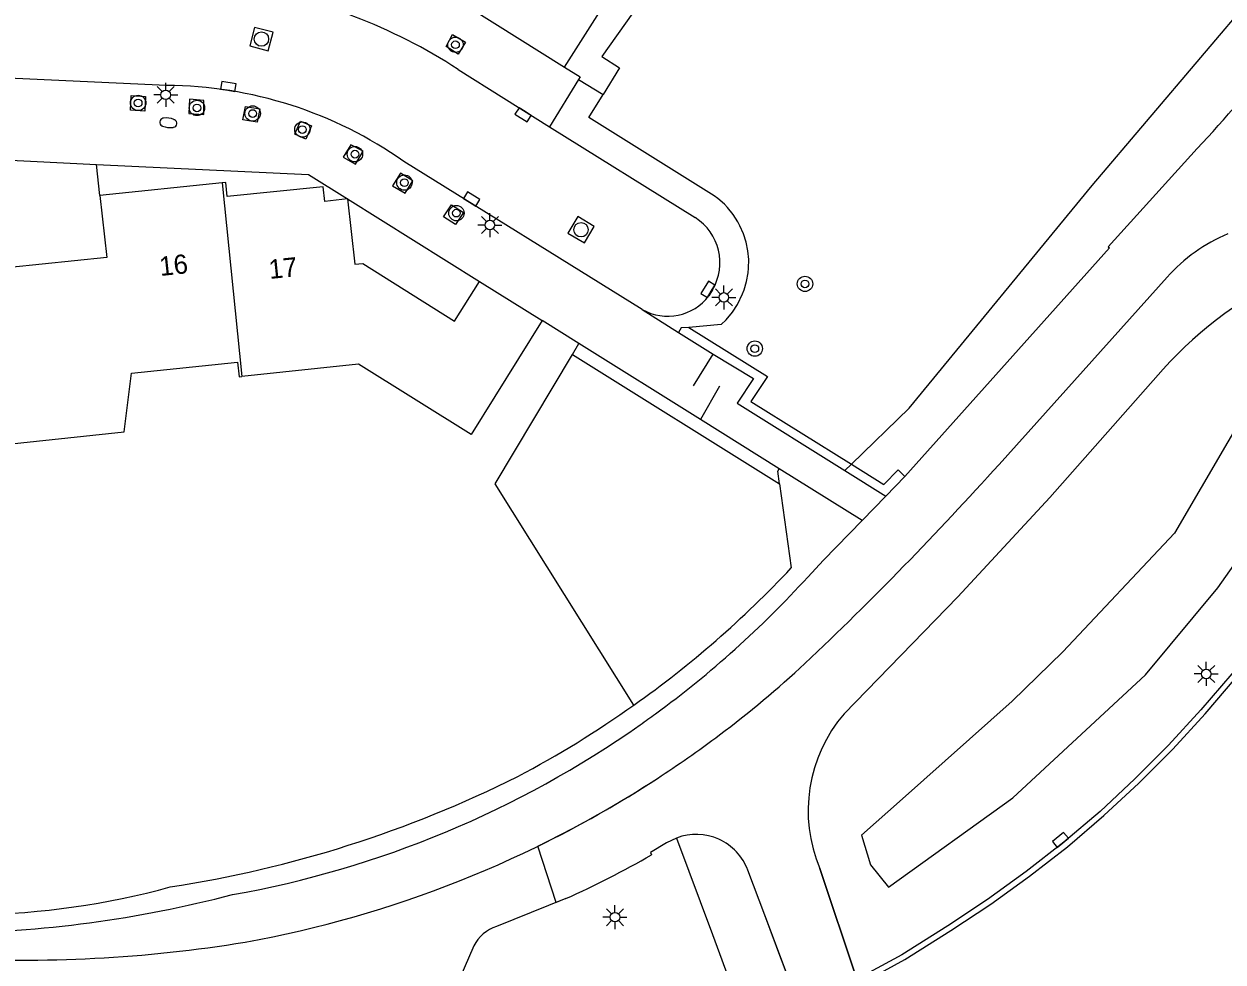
# Model space of a CAD drawing. Extents: x 132573 to 132944, y 398226 to 398676.
# Drawn here: x 132654.8 to 132717.2, y 398571.7 to 398620.6 of the extents above; entities that cross this region are included whole.
import ezdxf

# ---------------------------------------------------------------- set-up
doc = ezdxf.new("R2010")
doc.units = 0
for name, color, linetype in [('gg-afsc-erfafscheiding', 7, 'Continuous'), ('gg-afsc-hekwerk', 7, 'Continuous'), ('gg-anno-huisnummerreeks BGT', 7, 'Continuous'), ('gg-bbg-gedigitaliseerde bebouwing', 7, 'Continuous'), ('gg-bbg-hoofdgebouw', 7, 'Continuous'), ('gg-bbg-tussenscheiding', 7, 'Continuous'), ('gg-knt-BGT kruinlijn', 7, 'Continuous'), ('gg-knt-verharding', 7, 'Continuous'), ('gt-grn-groengrens', 7, 'Continuous'), ('gt-grn-vlakafsluiter', 7, 'Continuous'), ('gt-symb-boom', 7, 'Continuous'), ('gt-symb-brandkraan', 7, 'Continuous'), ('gt-symb-kolk', 7, 'Continuous'), ('gt-symb-lichtmast', 7, 'Continuous'), ('gt-symb-rioolschacht', 7, 'Continuous'), ('ir-asfa-asfalt arcering', 7, 'Continuous'), ('ir-asfa-asfalt rood', 7, 'Continuous')]:
    doc.layers.add(name, color=color, linetype=linetype)

msp = doc.modelspace()

# ---------------------------------------------------------------- linework, layer by layer
at = {"layer": 'gg-afsc-erfafscheiding'}
msp.add_line((132658.72, 398611.67), (132658.543, 398613.295), dxfattribs=at)
at = {"layer": 'gg-afsc-hekwerk'}
for p, q in [((132689.633, 398601.748), (132690.662, 398603.401)), ((132690.989, 398601.737), (132690.006, 398600.004))]:
    msp.add_line(p, q, dxfattribs=at)
msp.add_lwpolyline([(132690.662, 398603.401), (132692.765, 398602.136), (132691.907, 398600.848)], dxfattribs=at)
at = {"layer": 'gg-bbg-gedigitaliseerde bebouwing'}
for points in [[(132652.459, 398598.564), (132659.972, 398599.355), (132660.356, 398602.416), (132665.886, 398602.997), (132665.967, 398602.229), (132666.105, 398602.244)], [(132678.06, 398599.22), (132672.196, 398602.886), (132666.105, 398602.244)]]:
    msp.add_lwpolyline(points, dxfattribs=at)
at = {"layer": 'gg-bbg-hoofdgebouw'}
for p, q in [((132665.078, 398612.34), (132658.72, 398611.67)), ((132678.49, 398607.2), (132681.76, 398605.16)), ((132681.76, 398605.16), (132678.06, 398599.22))]:
    msp.add_line(p, q, dxfattribs=at)
for points in [[(132671.62, 398611.5), (132670.43, 398611.37), (132670.34, 398612.13), (132665.35, 398611.62), (132665.27, 398612.36), (132665.078, 398612.34)], [(132658.72, 398611.67), (132659.07, 398608.45), (132654.024, 398607.93)], [(132671.62, 398611.5), (132672, 398608.09), (132672.42, 398608.13), (132677.19, 398605.12), (132678.49, 398607.2)]]:
    msp.add_lwpolyline(points, dxfattribs=at)
at = {"layer": 'gg-bbg-tussenscheiding'}
msp.add_line((132665.078, 398612.34), (132666.105, 398602.244), dxfattribs=at)
at = {"layer": 'gg-knt-BGT kruinlijn'}
msp.add_lwpolyline([(132700.88, 398600.601), (132710.4, 398612.201), (132718.9, 398622.211), (132723.56, 398633.621), (132726.06, 398646.17), (132725.5, 398663.16), (132724.924, 398676.345)], dxfattribs=at)
at = {"layer": 'gg-knt-verharding'}
for p, q in [((132677.38, 398618.24), (132682.13, 398615.26)), ((132683.647, 398617.716), (132682.13, 398615.26)), ((132682.13, 398615.26), (132689.73, 398610.52)), ((132652.868, 398613.57), (132658.543, 398613.295)), ((132686.97, 398605.735), (132674.546, 398613.452)), ((132671.62, 398611.5), (132678.49, 398607.2)), ((132714.308, 398607.418), (132705.556, 398597.661)), ((132690.63, 398606.761), (132690.44, 398606.45)), ((132686.97, 398605.735), (132688.858, 398604.542)), ((132683.674, 398603.963), (132681.76, 398605.16)), ((132688.858, 398604.542), (132690.662, 398603.401)), ((132690.006, 398600.004), (132683.674, 398603.963)), ((132691.907, 398600.848), (132697.524, 398597.338)), ((132694.107, 398597.44), (132690.006, 398600.004)), ((132698.42, 398594.743), (132694.107, 398597.44)), ((132697.524, 398597.338), (132699.651, 398596.009)), ((132700.643, 398597.034), (132699.651, 398596.009)), ((132699.651, 398596.009), (132698.42, 398594.743)), ((132688.76, 398578.195), (132690.628, 398573.16)), ((132693.347, 398574.182), (132692.469, 398576.517)), ((132698.154, 398570.84), (132696.219, 398576.602)), ((132682.992, 398575.04), (132679.38, 398573.589)), ((132695.183, 398569.298), (132693.347, 398574.182)), ((132690.628, 398573.16), (132692.496, 398568.124))]:
    msp.add_line(p, q, dxfattribs=at)
for points in [[(132677.147, 398625.291), (132675.66, 398622.93), (132682.927, 398618.355)], [(132662.19, 398617.41), (132595.15, 398620.52), (132595.275, 398623.27)], [(132676.746, 398619.44), (132677.079, 398620.065), (132677.754, 398619.664), (132677.371, 398619.045), (132676.746, 398619.44)], [(132682.927, 398618.355), (132683.73, 398617.85), (132683.647, 398617.716)], [(132661.096, 398616.832), (132661.056, 398616.066), (132660.317, 398616.121), (132660.351, 398616.891), (132661.096, 398616.832)], [(132664.122, 398615.896), (132664.135, 398616.63), (132663.381, 398616.696), (132663.341, 398615.944), (132664.122, 398615.896)], [(132667.043, 398616.196), (132666.911, 398615.49), (132666.164, 398615.613), (132666.307, 398616.306), (132667.043, 398616.196)], [(132669.744, 398615.304), (132669.438, 398614.607), (132668.866, 398614.876), (132669.174, 398615.543), (132669.744, 398615.304)], [(132672.024, 398613.311), (132672.433, 398613.98), (132671.782, 398614.322), (132671.397, 398613.664), (132672.024, 398613.311)], [(132715.879, 398614.12), (132711.239, 398608.996), (132711.303, 398608.941), (132700.643, 398597.034)], [(132658.543, 398613.295), (132669.58, 398612.76), (132671.62, 398611.5)], [(132675.01, 398612.433), (132674.382, 398612.843), (132673.963, 398612.183), (132674.625, 398611.79), (132675.01, 398612.433)], [(132676.608, 398610.554), (132677.037, 398611.189), (132677.662, 398610.793), (132677.233, 398610.158), (132676.608, 398610.554)], [(132730.572, 398610.916), (132729.337, 398607.173), (132728.34, 398604.388), (132727.206, 398601.656), (132726.438, 398600.001), (132725.517, 398598.174), (132724.533, 398596.379), (132722.993, 398593.854), (132721.312, 398591.421), (132719.528, 398589.063), (132717.677, 398586.758), (132716.062, 398584.871), (132714.384, 398583.039), (132712.637, 398581.273), (132710.815, 398579.584), (132708.924, 398577.973), (132706.969, 398576.441), (132704.953, 398574.989), (132702.88, 398573.621), (132700.49, 398572.115), (132698.154, 398570.84)], [(132697.486, 398584.672), (132703.401, 398590.76), (132708.197, 398595.943), (132714.11, 398602.617)], [(132698.42, 398594.743), (132696.407, 398592.673), (132695.587, 398591.789)], [(132688.76, 398578.195), (132688.238, 398577.948), (132687.394, 398577.434), (132687.454, 398577.312)], [(132678.189, 398572.581), (132675.893, 398567.251), (132675.234, 398565.281), (132675.043, 398565.327), (132674.729, 398564.375)]]:
    msp.add_lwpolyline(points, dxfattribs=at)
for centre, radius, start, end in [((132661.551, 398593.889), 29.044, 56.97532, 81.06504), ((132671.99, 398655.469), 60.299, 316.7067, 322.88785), ((132662.078, 398595.796), 21.614, 54.77229, 89.70404), ((132688.236, 398608.175), 2.781, 329.43694, 57.49226), ((132720.916, 398601.484), 8.881, 112.80033, 138.07276), ((132728.52, 398589.916), 19.208, 112.73249, 138.60618), ((132688.298, 398608.069), 2.685, 240.36053, 322.92537), ((132568.326, 398721.233), 184.668, 313.50095, 317.99777), ((132656.302, 398627.54), 53.117, 306.1857, 317.69598), ((132656.058, 398629.979), 58.089, 306.97878, 312.69066), ((132656.343, 398627.49), 53.052, 305.12427, 306.18226), ((132703.375, 398579.613), 7.764, 139.33593, 202.81873), ((132656.287, 398627.555), 53.138, 280.11435, 305.13303), ((132656.82, 398628.883), 56.756, 304.96329, 307.02972), ((132655.731, 398630.425), 58.643, 303.10779, 304.97198), ((132655.948, 398630.108), 58.259, 280.22415, 303.09962), ((132689.779, 398575.509), 2.873, 20.53771, 110.77705), ((132661.858, 398622.062), 51.553, 294.20115, 299.76822), ((132649.817, 398635.89), 62.672, 270.71597, 284.60424), ((132680.079, 398571.556), 2.15, 108.96629, 151.51937), ((132654.857, 398641.739), 69.906, 266.47629, 279.41239)]:
    msp.add_arc(centre, radius, start, end, dxfattribs=at)
at = {"layer": 'gt-grn-groengrens'}
for p, q in [((132683.647, 398617.716), (132684.93, 398616.938)), ((132691.083, 398604.946), (132689.394, 398604.803)), ((132683.334, 398603.392), (132683.674, 398603.963)), ((132683.334, 398603.392), (132694.116, 398596.651)), ((132697.867, 398597.673), (132700.88, 398600.601)), ((132697.867, 398597.673), (132697.524, 398597.338)), ((132694.116, 398596.651), (132694.728, 398592.268))]:
    msp.add_line(p, q, dxfattribs=at)
for points in [[(132712.864, 398676.345), (132713.509, 398668.488), (132703.529, 398650.723), (132695.115, 398635.922), (132694.094, 398631.191), (132691.582, 398628.079), (132686.56, 398621.124), (132686.482, 398621.186), (132684.863, 398618.909), (132685.788, 398618.327), (132684.93, 398616.938)], [(132691.083, 398604.946), (132691.345, 398605.199), (132691.671, 398605.588), (132691.924, 398606.001), (132692.194, 398606.542), (132692.277, 398606.762), (132692.404, 398607.198), (132692.485, 398607.648), (132692.507, 398607.883), (132692.515, 398608.336), (132692.472, 398608.794), (132692.38, 398609.248), (132692.242, 398609.683), (132692.06, 398610.1), (132691.949, 398610.307), (132691.7, 398610.691), (132691.411, 398611.047), (132691.251, 398611.214), (132690.915, 398611.515), (132690.724, 398611.659), (132684.191, 398615.742), (132684.93, 398616.938)], [(132706.238, 398585.328), (132700.524, 398580.236), (132698.397, 398578.341), (132698.865, 398576.798), (132699.804, 398575.637), (132706.276, 398580.281), (132713.192, 398586.704), (132716.947, 398591.224), (132721.989, 398598.375), (132723.82, 398603.024), (132724.452, 398604.629), (132723.622, 398605.26), (132721.995, 398604.844), (132719.838, 398602.875), (132717.889, 398599.543), (132717.479, 398598.843), (132714.696, 398594.086), (132708.872, 398587.901), (132706.238, 398585.328)], [(132689.394, 398604.803), (132689.002, 398604.77), (132688.858, 398604.542)], [(132689.394, 398604.803), (132693.494, 398602.24), (132692.631, 398600.945), (132697.867, 398597.673)], [(132686.538, 398585.123), (132679.312, 398596.642), (132683.334, 398603.392)], [(132694.116, 398596.651), (132694.024, 398597.308), (132694.107, 398597.44)], [(132697.867, 398597.673), (132699.559, 398596.615), (132700.295, 398597.372), (132700.643, 398597.034)]]:
    msp.add_lwpolyline(points, dxfattribs=at)
for centre, radius, start, end in [((132655.202, 398629.308), 54.169, 305.34389, 316.85935), ((132655.173, 398629.383), 54.247, 297.80881, 305.32384), ((132653.185, 398635.878), 60.932, 278.68302, 296.61252), ((132651.678, 398614.585), 40.385, 270.78693, 285.37212)]:
    msp.add_arc(centre, radius, start, end, dxfattribs=at)
at = {"layer": 'gt-grn-vlakafsluiter'}
msp.add_line((132682.927, 398618.355), (132686.26, 398623.65), dxfattribs=at)
at = {"layer": 'gt-symb-boom'}
for centre, radius in [((132677.24, 398619.527), 0.4), ((132677.24, 398619.527), 0.2), ((132660.709, 398616.496), 0.4), ((132660.709, 398616.496), 0.2), ((132663.773, 398616.236), 0.4), ((132663.773, 398616.236), 0.2), ((132666.675, 398615.946), 0.4), ((132666.675, 398615.946), 0.2), ((132669.264, 398615.11), 0.4), ((132669.264, 398615.11), 0.2), ((132672.003, 398613.828), 0.4), ((132672.003, 398613.828), 0.2), ((132674.578, 398612.345), 0.4), ((132674.578, 398612.345), 0.2), ((132677.29, 398610.754), 0.4), ((132677.29, 398610.754), 0.2), ((132695.447, 398607.068), 0.4), ((132695.447, 398607.068), 0.2), ((132692.832, 398603.695), 0.4), ((132692.832, 398603.695), 0.2)]:
    msp.add_circle(centre, radius, dxfattribs=at)
at = {"layer": 'gt-symb-brandkraan'}
for centre, radius, start, end in [((132662.035, 398615.494), 0.206, 100.03668, 244.90282), ((132662.522, 398612.742), 3, 99.36179, 100.03668), ((132662.186, 398614.777), 0.938, 65.57773, 99.36179), ((132662.519, 398615.43), 0.206, 280.0367, 64.90283), ((132661.334, 398612.899), 3, 64.90283, 65.57773), ((132663.22, 398618.025), 3, 244.90282, 245.57772), ((132662.368, 398616.147), 0.938, 245.57772, 279.36181), ((132662.032, 398618.182), 3, 279.36181, 280.0367)]:
    msp.add_arc(centre, radius, start, end, dxfattribs=at)
at = {"layer": 'gt-symb-kolk'}
for points in [[(132665.378, 398617.154), (132665.749, 398617.097), (132665.809, 398617.493), (132665.068, 398617.606), (132665.007, 398617.211), (132665.378, 398617.154)], [(132680.87, 398616.05), (132680.552, 398616.249), (132680.34, 398615.911), (132680.975, 398615.512), (132681.188, 398615.851), (132680.87, 398616.05)], [(132677.973, 398611.323), (132678.292, 398611.125), (132678.502, 398611.465), (132677.865, 398611.861), (132677.654, 398611.521), (132677.973, 398611.323)], [(132690.563, 398606.682), (132690.758, 398607.002), (132690.416, 398607.21), (132690.026, 398606.57), (132690.368, 398606.362), (132690.563, 398606.682)], [(132708.88, 398577.941), (132709.171, 398578.178), (132708.919, 398578.488), (132708.337, 398578.015), (132708.589, 398577.704), (132708.88, 398577.941)]]:
    msp.add_lwpolyline(points, dxfattribs=at)
at = {"layer": 'gt-symb-lichtmast'}
for p, q in [((132662.143, 398617.169), (132662.143, 398617.544)), ((132661.893, 398616.919), (132661.518, 398616.919)), ((132661.966, 398617.096), (132661.701, 398617.361)), ((132662.32, 398617.096), (132662.585, 398617.361)), ((132662.393, 398616.919), (132662.768, 398616.919)), ((132661.966, 398616.742), (132661.701, 398616.477)), ((132662.143, 398616.669), (132662.143, 398616.294)), ((132662.585, 398616.477), (132662.32, 398616.742)), ((132678.854, 398610.313), (132678.589, 398610.578)), ((132679.031, 398610.386), (132679.031, 398610.761)), ((132679.208, 398610.313), (132679.473, 398610.578)), ((132678.781, 398610.136), (132678.406, 398610.136)), ((132678.854, 398609.959), (132678.589, 398609.694)), ((132679.473, 398609.694), (132679.208, 398609.959)), ((132679.281, 398610.136), (132679.656, 398610.136)), ((132679.031, 398609.886), (132679.031, 398609.511)), ((132691.22, 398606.612), (132691.22, 398606.987)), ((132690.97, 398606.362), (132690.595, 398606.362)), ((132691.043, 398606.539), (132690.778, 398606.804)), ((132691.043, 398606.185), (132690.778, 398605.92)), ((132691.397, 398606.539), (132691.662, 398606.804)), ((132691.662, 398605.92), (132691.397, 398606.185)), ((132691.47, 398606.362), (132691.845, 398606.362)), ((132691.22, 398606.112), (132691.22, 398605.737)), ((132716.17, 398586.919), (132715.905, 398587.184)), ((132716.347, 398586.992), (132716.347, 398587.367)), ((132716.524, 398586.919), (132716.789, 398587.184)), ((132716.097, 398586.742), (132715.722, 398586.742)), ((132716.17, 398586.565), (132715.905, 398586.3)), ((132716.347, 398586.492), (132716.347, 398586.117)), ((132716.789, 398586.3), (132716.524, 398586.565)), ((132716.597, 398586.742), (132716.972, 398586.742)), ((132685.371, 398574.246), (132685.106, 398574.511)), ((132685.548, 398574.319), (132685.548, 398574.694)), ((132685.725, 398574.246), (132685.99, 398574.511)), ((132685.298, 398574.069), (132684.923, 398574.069)), ((132685.371, 398573.892), (132685.106, 398573.627)), ((132685.548, 398573.819), (132685.548, 398573.444)), ((132685.99, 398573.627), (132685.725, 398573.892)), ((132685.798, 398574.069), (132686.173, 398574.069))]:
    msp.add_line(p, q, dxfattribs=at)
for centre in [(132662.143, 398616.919), (132679.031, 398610.136), (132691.22, 398606.362), (132716.347, 398586.742), (132685.548, 398574.069)]:
    msp.add_circle(centre, 0.25, dxfattribs=at)
at = {"layer": 'gt-symb-rioolschacht'}
for points in [[(132666.52, 398619.469), (132667.487, 398619.214), (132667.742, 398620.181), (132666.775, 398620.436)], [(132684.464, 398610.063), (132683.606, 398610.575), (132683.094, 398609.717), (132683.952, 398609.205)]]:
    msp.add_lwpolyline(points, close=True, dxfattribs=at)
for centre in [(132667.131, 398619.825), (132683.779, 398609.89)]:
    msp.add_circle(centre, 0.375, dxfattribs=at)
at = {"layer": 'ir-asfa-asfalt arcering'}
msp.add_lwpolyline([(132711.618, 398563.207), (132711.453, 398566.5), (132707.16, 398564.631), (132700.85, 398562.321), (132698.246, 398570.55), (132698.292, 398570.574), (132698.298, 398570.577), (132700.642, 398571.856), (132703.043, 398573.369), (132705.123, 398574.742), (132707.149, 398576.201), (132709.114, 398577.741), (132711.014, 398579.36), (132712.846, 398581.057), (132714.601, 398582.832), (132716.287, 398584.672), (132717.908, 398586.566)], dxfattribs=at)
at = {"layer": 'ir-asfa-asfalt rood'}
msp.add_line((132705.556, 398597.661), (132714.308, 398607.418), dxfattribs=at)
for points in [[(132714.11, 398602.617), (132708.197, 398595.943), (132703.401, 398590.76), (132697.486, 398584.672)], [(132688.76, 398578.195), (132688.238, 398577.948), (132687.394, 398577.434), (132687.454, 398577.312)], [(132682.992, 398575.04), (132682.489, 398574.838), (132681.524, 398577.763)], [(132694.245, 398571.794), (132693.347, 398574.182), (132692.469, 398576.517)], [(132696.219, 398576.602), (132698.154, 398570.84), (132695.183, 398569.298), (132694.255, 398571.768)]]:
    msp.add_lwpolyline(points, dxfattribs=at)
for centre, radius, start, end in [((132720.916, 398601.484), 8.881, 112.80033, 138.07276), ((132728.52, 398589.916), 19.208, 112.73249, 138.60618), ((132568.326, 398721.233), 184.668, 313.50095, 317.99777), ((132656.058, 398629.979), 58.089, 306.97878, 312.69066), ((132703.375, 398579.613), 7.764, 139.33593, 202.81873), ((132656.82, 398628.883), 56.756, 304.96329, 307.02972), ((132655.731, 398630.425), 58.643, 303.10779, 304.97198), ((132655.948, 398630.108), 58.259, 296.04082, 303.09962), ((132689.779, 398575.509), 2.873, 20.53771, 110.77705), ((132661.858, 398622.062), 51.553, 294.20115, 299.76822), ((132694.016, 398571.693), 0.25, 17.41642, 23.7882)]:
    msp.add_arc(centre, radius, start, end, dxfattribs=at)

# ---------------------------------------------------------------- texts
at = {"layer": 'gg-anno-huisnummerreeks BGT'}
for s, rotation, p in [('16', 6, (132661.865, 398607.477)), ('17', 5.9, (132667.562, 398607.322))]:
    msp.add_text(s, height=1, rotation=rotation, dxfattribs=at).set_placement(p)

doc.saveas('drawing.dxf')
